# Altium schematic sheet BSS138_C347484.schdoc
size 127 x 101 mm
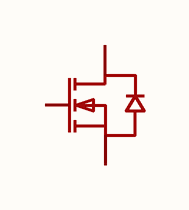
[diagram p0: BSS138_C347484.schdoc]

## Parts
Q?  bss138_c347484  [SOT-23-3_L2.9-W1.6-P1.90-LS2.8-BR]  (value not drawn)

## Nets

Not connected (* = marked no-connect by the designer): Q? 1(G) 2(S) 3(D)

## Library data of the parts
Q? = bss138_c347484: 数量:1个N沟道;漏源电压(Vdss):50V;连续漏极电流(Id):300mA;导通电阻(RDS(on)):2.5Ω@10V；3.5Ω@2.5V;耗散功率(Pd):300mW;阈值电压(Vgs(th)):1.5V@250uA;; Manufacturer: UMW(友台半导体); ManufacturerPart: BSS138; AddInBom: yes; ModelId: 89cb27a44ab2466697082bb9fd73a7d0; ModelName: SOT-23-3L_L2.9-W1.6-H1.1-LS2.8-P0.95; ModelTransform: 114.173,110.236,0,90,0,0,0,0,0; Number: 1个N沟道; Drain to Source Voltage: 50V; Current - Continuous Drain(Id): 300mA; Pd - Power Dissipation: 300mW; Input Capacitance(Ciss): 50pF; Reverse Transfer Capacitance (Crss@Vds): 8pF; Type: N沟道; Output Capacitance(Coss): 25pF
